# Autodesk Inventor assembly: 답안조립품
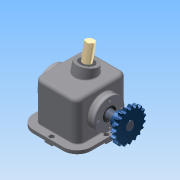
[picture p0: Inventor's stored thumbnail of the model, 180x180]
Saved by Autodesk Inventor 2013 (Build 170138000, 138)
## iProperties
Created: 2014-11
Part Number: 답안조립품
Document SubType Name: Assembly
Designer: Administrator
Author: Administrator
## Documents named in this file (13)
- C:\Users\Administrator\Desktop\441123V1005\답안조립품.iam
- C:\Users\Administrator\Desktop\441123V1005\1. 본체.ipt
- C:\Users\Administrator\Desktop\441123V1005\앞커버.ipt
- C:\Users\Administrator\Desktop\441123V1005\오일실.ipt
- C:\Users\Administrator\Desktop\441123V1005\뒤커버.ipt
- C:\Users\Administrator\Desktop\441123V1005\베어링 6205.ipt
- C:\Users\Administrator\Desktop\441123V1005\편심축.ipt
- C:\Users\Administrator\Desktop\441123V1005\슬라이드.ipt
- C:\Users\Administrator\Desktop\441123V1005\부시.ipt
- C:\Users\Administrator\Desktop\441123V1005\5-체인 스프로킷.ipt
- C:\Users\Administrator\Desktop\441123V1005\키 8x8.ipt
- C:\Users\Administrator\Desktop\441123V1005\멈춤나사 M5x0.5.ipt
- C:\Users\Administrator\Desktop\441123V1005\M4x0.5.ipt
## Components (10 placed, 3 different names)
1. 1. 본체:1
2. 5-체인 스프로킷:1 — 플러쉬:1
3. M4x0.5:1
4. M4x0.5:2
5. M4x0.5:3
6. M4x0.5:4
7. M4x0.5:5
8. M4x0.5:6
9. M4x0.5:7
10. M4x0.5:8
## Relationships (1: Flush 1)
- 플러쉬:1 [Flush]: 5-체인 스프로킷:1
